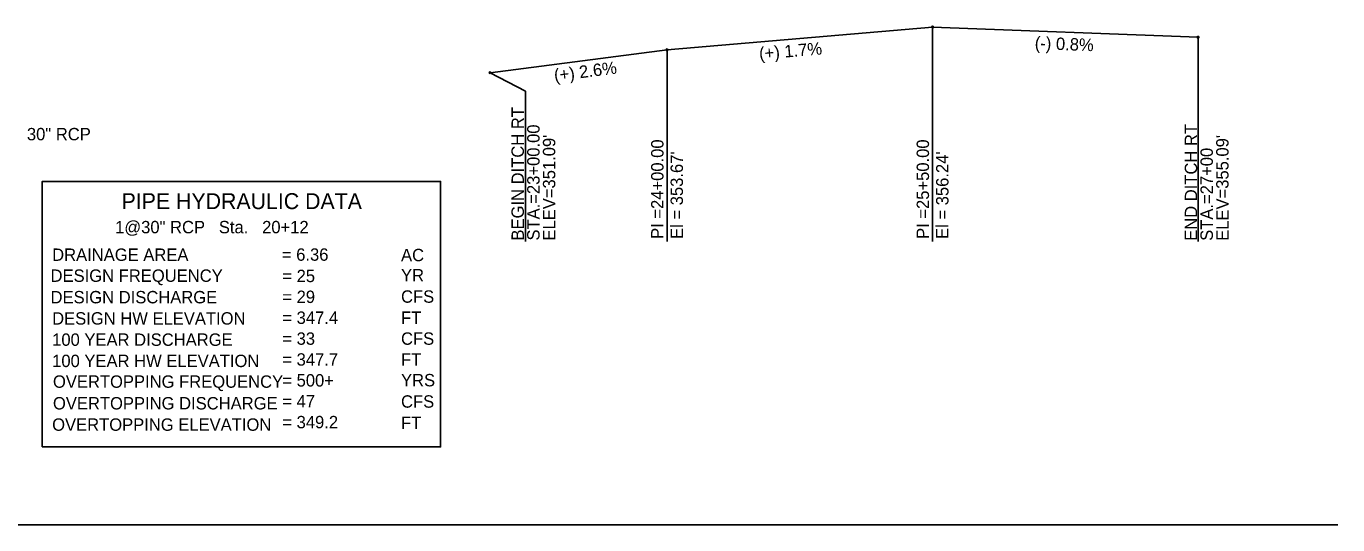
# Model space of a CAD drawing. Extents: x 2044939 to 2046718, y 752715 to 754848.
# Drawn here: x 2045977 to 2046718, y 752715 to 752997 of the extents above; entities that cross this region are included whole.
import ezdxf

# ---------------------------------------------------------------- set-up
doc = ezdxf.new("R2010")
doc.units = 0
for name, color, linetype in [('Exist Profile Cell', 7, 'Continuous'), ('Prop Grid Mask', 7, 'Continuous'), ('Prop PFL Cross Pipe Text CELL', 7, 'Continuous'), ('Prop PFL Pipe Hydraulic Data CELL', 7, 'Continuous'), ('Prop Vertical Profile Ditch Grade Right', 7, 'Continuous'), ('Prop Vertical Profile Ditch Grade Right Label', 7, 'Continuous'), ('Prop VPI Ditch Grade Right Label', 7, 'Continuous')]:
    doc.layers.add(name, color=color, linetype=linetype)

msp = doc.modelspace()

# ---------------------------------------------------------------- linework, layer by layer
at = {"layer": 'Exist Profile Cell'}
msp.add_line((2044939.41, 752715.24), (2046718.32, 752715.24), dxfattribs=at)
at = {"layer": 'Prop Grid Mask'}
msp.add_lwpolyline([(2045986.48, 752759.25), (2046211.48, 752759.25), (2046211.48, 752909.25), (2045986.48, 752909.25)], close=True, dxfattribs=at)
at = {"layer": 'Prop Vertical Profile Ditch Grade Right'}
msp.add_lwpolyline([(2046239.41, 752970.69), (2046339.41, 752983.59), (2046489.41, 752996.44), (2046639.41, 752990.69)], dxfattribs=at)
at = {"layer": 'Prop VPI Ditch Grade Right Label'}
for p, q in [((2046489.41, 752996.44), (2046489.41, 752875.24)), ((2046639.41, 752990.69), (2046639.41, 752875.24)), ((2046339.41, 752983.59), (2046339.41, 752875.24))]:
    msp.add_line(p, q, dxfattribs=at)
msp.add_lwpolyline([(2046239.41, 752970.69), (2046259.41, 752960.24), (2046259.41, 752875.24)], dxfattribs=at)
for centre in [(2046489.41, 752996.44), (2046639.41, 752990.69), (2046339.41, 752983.59), (2046239.41, 752970.69)]:
    msp.add_circle(centre, 0.5, dxfattribs=at)

# ---------------------------------------------------------------- texts
at = {"layer": 'Prop PFL Cross Pipe Text CELL'}
msp.add_text('30" RCP', height=7, dxfattribs=at).set_placement((2045977.78, 752932.47))
at = {"layer": 'Prop PFL Pipe Hydraulic Data CELL'}
for s, height, p in [('PIPE HYDRAULIC DATA', 8.9997, (2046031.28, 752893.6)), (' 1@30" RCP   Sta.   20+12   ', 6.9996, (2046025.01, 752879.93)), ('DRAINAGE AREA', 6.9999, (2045992.05, 752864.35)), ('= 6.36   ', 7, (2046121.84, 752864.43)), ('AC', 7, (2046189.14, 752864.15)), ('DESIGN FREQUENCY', 6.9999, (2045991.15, 752852.5)), ('= 25 ', 7, (2046122.08, 752852.35)), ('YR', 7, (2046189.14, 752852.75)), ('DESIGN DISCHARGE', 6.9999, (2045991.15, 752840.35)), ('= 29      ', 7, (2046122.08, 752840.55)), ('CFS', 7, (2046189.14, 752840.7)), ('DESIGN HW ELEVATION', 6.9999, (2045992.05, 752828.35)), ('= 347.4   ', 7, (2046122.08, 752828.75)), ('FT', 7, (2046189.14, 752828.75)), ('= 33      ', 7, (2046122.08, 752816.95)), ('CFS', 7, (2046189.14, 752816.95)), ('100 YEAR DISCHARGE', 6.9999, (2045992.05, 752816.35)), ('100 YEAR HW ELEVATION', 6.9999, (2045992.05, 752804.35)), ('= 347.7   ', 7, (2046122.08, 752805.15)), ('FT', 7, (2046189.14, 752805.15)), ('OVERTOPPING FREQUENCY', 6.9999, (2045992.5, 752792.65)), ('= 500+', 7, (2046122.08, 752793.35)), ('YRS', 7, (2046189.14, 752793.45)), ('OVERTOPPING DISCHARGE', 6.9999, (2045992.5, 752780.4)), ('= 47      ', 7, (2046122.08, 752781.55)), ('CFS', 7, (2046189.14, 752781.4)), ('OVERTOPPING ELEVATION', 6.9999, (2045992.05, 752768.35)), ('= 349.2   ', 7, (2046122.08, 752769.75)), ('FT', 7, (2046189.14, 752769.35))]:
    msp.add_text(s, height=height, dxfattribs=at).set_placement(p)
at = {"layer": 'Prop Vertical Profile Ditch Grade Right Label'}
for s, rotation, p in [('(+) 1.7%', 4.89638, (2046391.72, 752977.98)), ('(-) 0.8%', 357.80474, (2046547.06, 752984.07)), ('(+) 2.6%', 7.35056, (2046276.03, 752965.68))]:
    msp.add_text(s, height=7, rotation=rotation, dxfattribs=at).set_placement(p)
at = {"layer": 'Prop VPI Ditch Grade Right Label'}
for s, p in [('BEGIN DITCH RT', (2046258.54, 752875.84)), ('STA.=23+00.00', (2046267.41, 752875.84)), ("ELEV=351.09'", (2046276.29, 752875.84)), ('END DITCH RT', (2046638.89, 752875.68)), ("ELEV=355.09'", (2046656.63, 752875.68)), ('PI =24+00.00', (2046337.41, 752876.77)), ('PI =25+50.00', (2046487.41, 752876.76)), ('STA.=27+00', (2046647.76, 752875.68)), ("El = 353.67'", (2046348.41, 752876.77)), ("El = 356.24'", (2046498.41, 752876.76))]:
    msp.add_text(s, height=7, rotation=90, dxfattribs=at).set_placement(p)

doc.saveas('drawing.dxf')
